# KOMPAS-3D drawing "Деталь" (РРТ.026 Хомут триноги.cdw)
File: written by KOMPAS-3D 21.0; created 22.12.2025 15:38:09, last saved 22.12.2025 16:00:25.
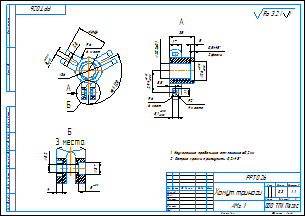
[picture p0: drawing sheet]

Sheet 1: A4x2, landscape

Document properties: Автор: User; Полное имя файла: C:\Users\User\Desktop\Ручной ротатор КД\Чертежи\РРТ.026 Хомут триноги.cdw; Знак неуказанной шероховатости: 4; Параметр неуказанной шероховатости: Ra 3.2; Масса: 0.295818; Форматы листов документа: A4@4~2

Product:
- Part/product: Деталь
    Масса: 0.295818
  - Body: Тело 1
      Масса: 0.296152

Title block, sheet 1: Наименование: Хомут триноги; designation: РРТ.026; Материал: АМг 1; Масса: 0,3; Количество листов документа: 1; organisation: ООО ТПК Пегас; Форматы листов документа: A4 2

Views: Вид 1, Местный разрез 1, Сверху, Вид по стрелке 2, Выносной элемент Б, Выносной элемент
Referenced files in C:\Users\User\Desktop\Ручной ротатор КД\Тринога\: Хомут.m3d
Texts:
  шаг
  Ra 3.2
  Ra 3.2 ( )
Dimensions and other numbers on the sheet: 40,35; 20; 6; 36; 120; 6 мест; 20,2±0,1; 26; 8,1; 11; 2; 4 места; 29,4; 17; 8,5; 35; 5; 0,5; 2 фаски; 1:1; 1; 0,3

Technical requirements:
  Неуказанные предельные отклонения  0,2мм
  Острые кромки притиупить 0,2х45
